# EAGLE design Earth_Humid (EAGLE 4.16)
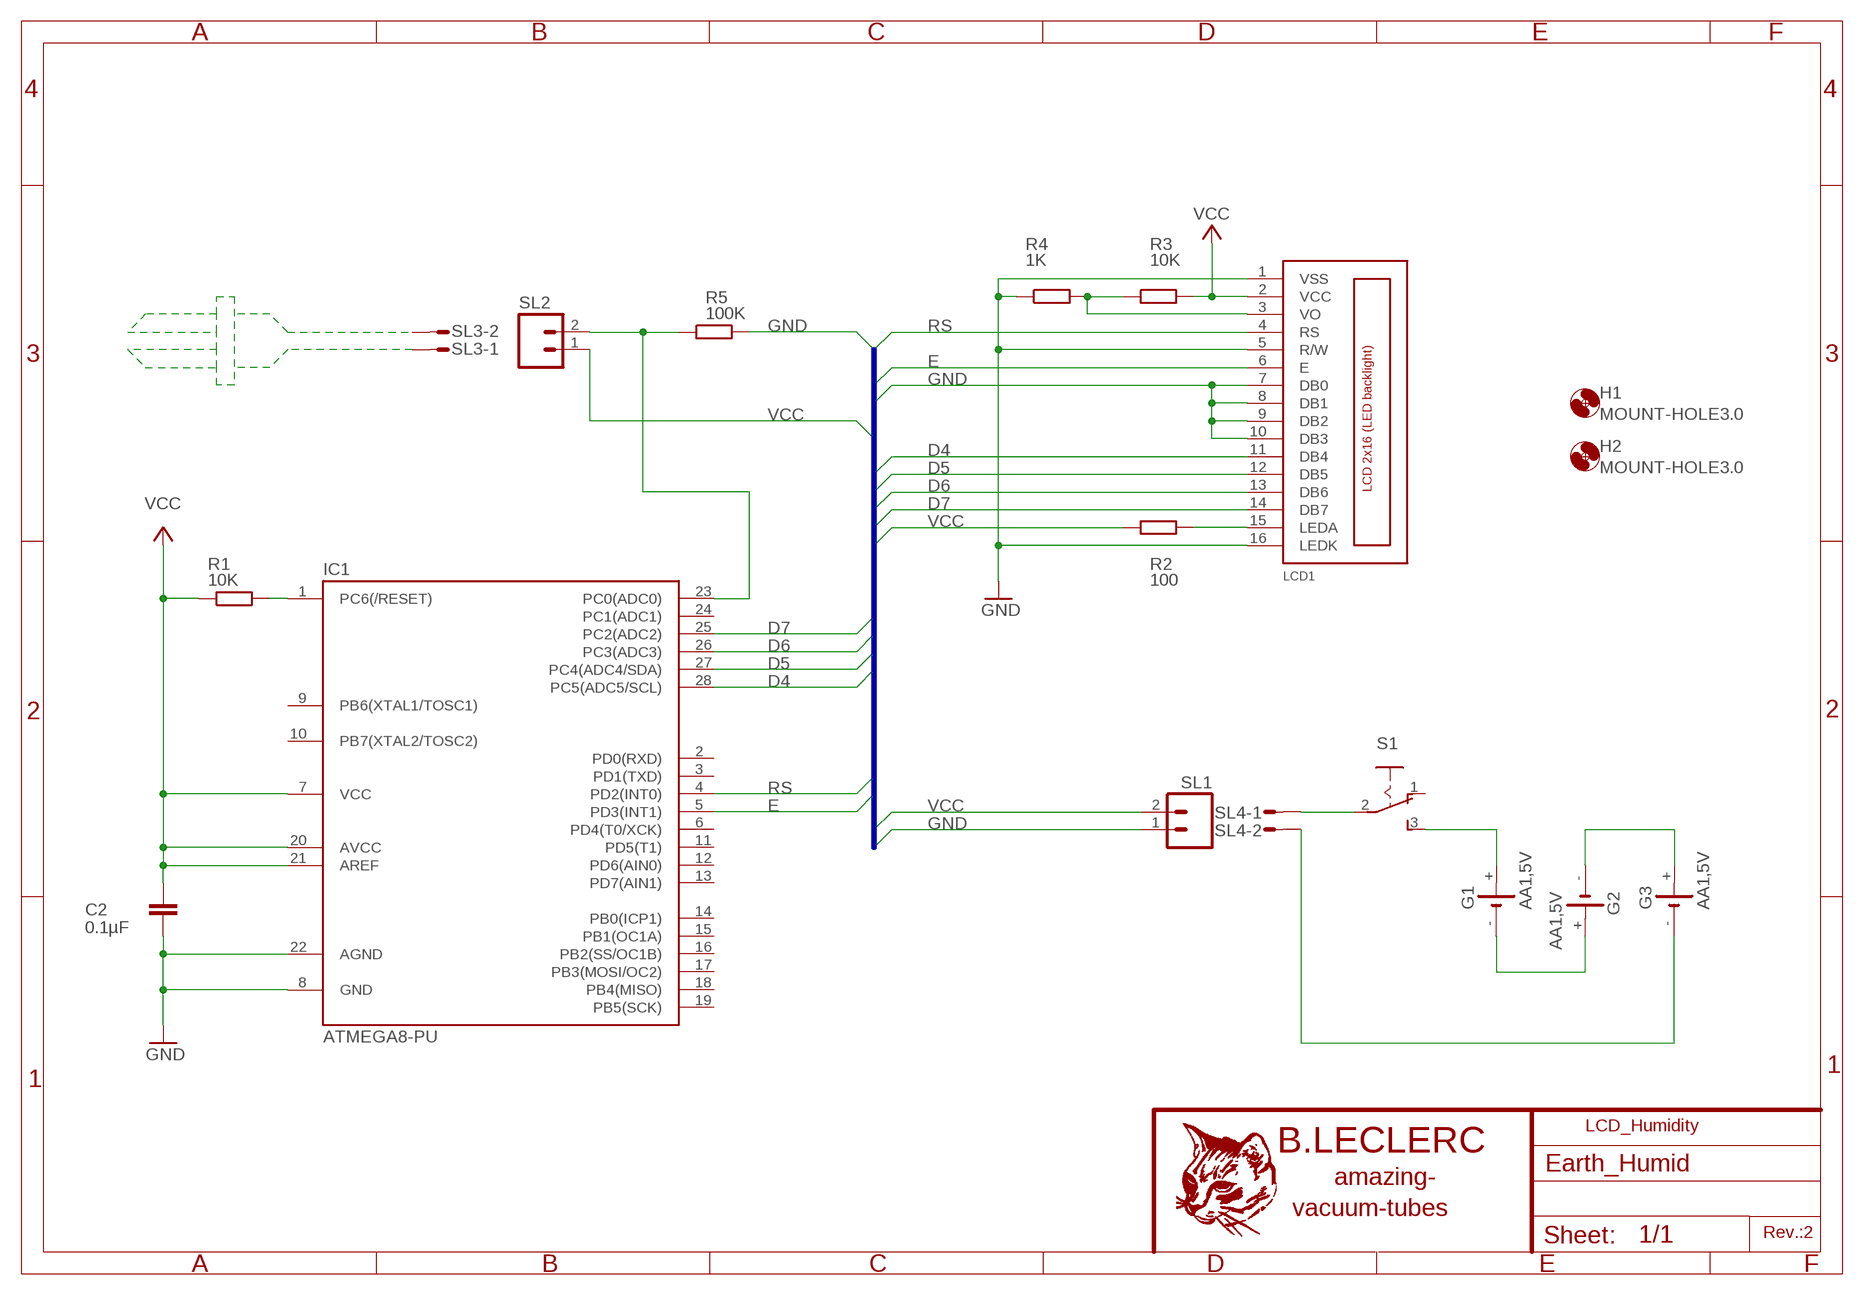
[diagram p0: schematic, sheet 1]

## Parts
C2  0.1µF  C-EU050-025X075  [C050-025X075]
G1  AA1,5V  SL-160AA/PR  [SL-160AA/PR]
G2  AA1,5V  SL-160AA/PR  [SL-160AA/PR]
G3  AA1,5V  SL-160AA/PR  [SL-160AA/PR]
H1  MOUNT-HOLE3.0  [3,0]
H2  MOUNT-HOLE3.0  [3,0]
IC1  ATMEGA8-PU  [DIL28-3]
LCD1  LCD_2X16_SIL  [HY-1602F]
R1  10K  R-EU_0207/10  [0207/10]
R2  100  R-EU_0207/10  [0207/10]
R3  10K  R-EU_0207/10  [0207/10]
R4  1K  R-EU_0207/10  [0207/10]
R5  100K  R-EU_0207/10  [0207/10]
S1  255SB  [255SB]
SL1  M02  [02P]
SL2  M02  [02P]
SL3  M02S  [02P]
SL4  M02S  [02P]

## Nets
D4: IC1.28(PC5(ADC5/SCL)) LCD1.11(DB4)
D5: IC1.27(PC4(ADC4/SDA)) LCD1.12(DB5)
D6: IC1.26(PC3(ADC3)) LCD1.13(DB6)
D7: IC1.25(PC2(ADC2)) LCD1.14(DB7)
E: IC1.5(PD3(INT1)) LCD1.6(E)
GND: C2.2 IC1.8(GND) IC1.22(AGND) LCD1.1(VSS) LCD1.5(R/W) LCD1.7(DB0) LCD1.8(DB1) LCD1.9(DB2) LCD1.10(DB3) LCD1.16(LEDK) R4.1 R5.2 SL1.1
N$1: S1.2(P) SL4.1
N$2: G1.+ S1.3(S)
N$3: IC1.1(PC6(/RESET)) R1.2
N$4: LCD1.3(VO) R3.1 R4.2
N$5: LCD1.15(LEDA) R2.2
N$6: IC1.23(PC0(ADC0)) R5.1 SL2.2
N$7: G1.- G2.+
N$8: G2.- G3.+
N$9: G3.- SL4.2
N$11: SL3.2
N$39: SL3.1
RS: IC1.4(PD2(INT0)) LCD1.4(RS)
VCC: C2.1 IC1.7(VCC) IC1.20(AVCC) IC1.21(AREF) LCD1.2(VCC) R1.1 R2.1 R3.2 SL1.2 SL2.1
Unconnected: IC1.2(PD0(RXD)) IC1.3(PD1(TXD)) IC1.6(PD4(T0/XCK)) IC1.9(PB6(XTAL1/TOSC1)) IC1.10(PB7(XTAL2/TOSC2)) IC1.11(PD5(T1)) IC1.12(PD6(AIN0)) IC1.13(PD7(AIN1)) IC1.14(PB0(ICP1)) IC1.15(PB1(OC1A)) IC1.16(PB2(SS/OC1B)) IC1.17(PB3(MOSI/OC2)) IC1.18(PB4(MISO)) IC1.19(PB5(SCK)) IC1.24(PC1(ADC1)) S1.1(O)

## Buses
B$1

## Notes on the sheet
- LCD_Humidity
- Rev.:2

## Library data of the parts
C2 = rcl:C-EU: CAPACITOR, European symbol
G1-G3 = battery:SL-160AA/PR: LI BATTERY Sonnenschein
H1 H2 = holes:MOUNT-HOLE: MOUNTING HOLE with drill center marker
IC1 = atmega8:ATMEGA8-PU
LCD1 = lcd_2x16_led_backlight:LCD_2X16_SIL
R1-R5 = rcl:R-EU_: RESISTOR, European symbol
S1 = switch:255SB: SLIDING SWITCH distributor Buerklin, 11G810
SL1 SL2 = con-NANARD:M02: AMP QUICK CONNECTOR
SL3 SL4 = con-NANARD:M02S: AMP QUICK CONNECTOR

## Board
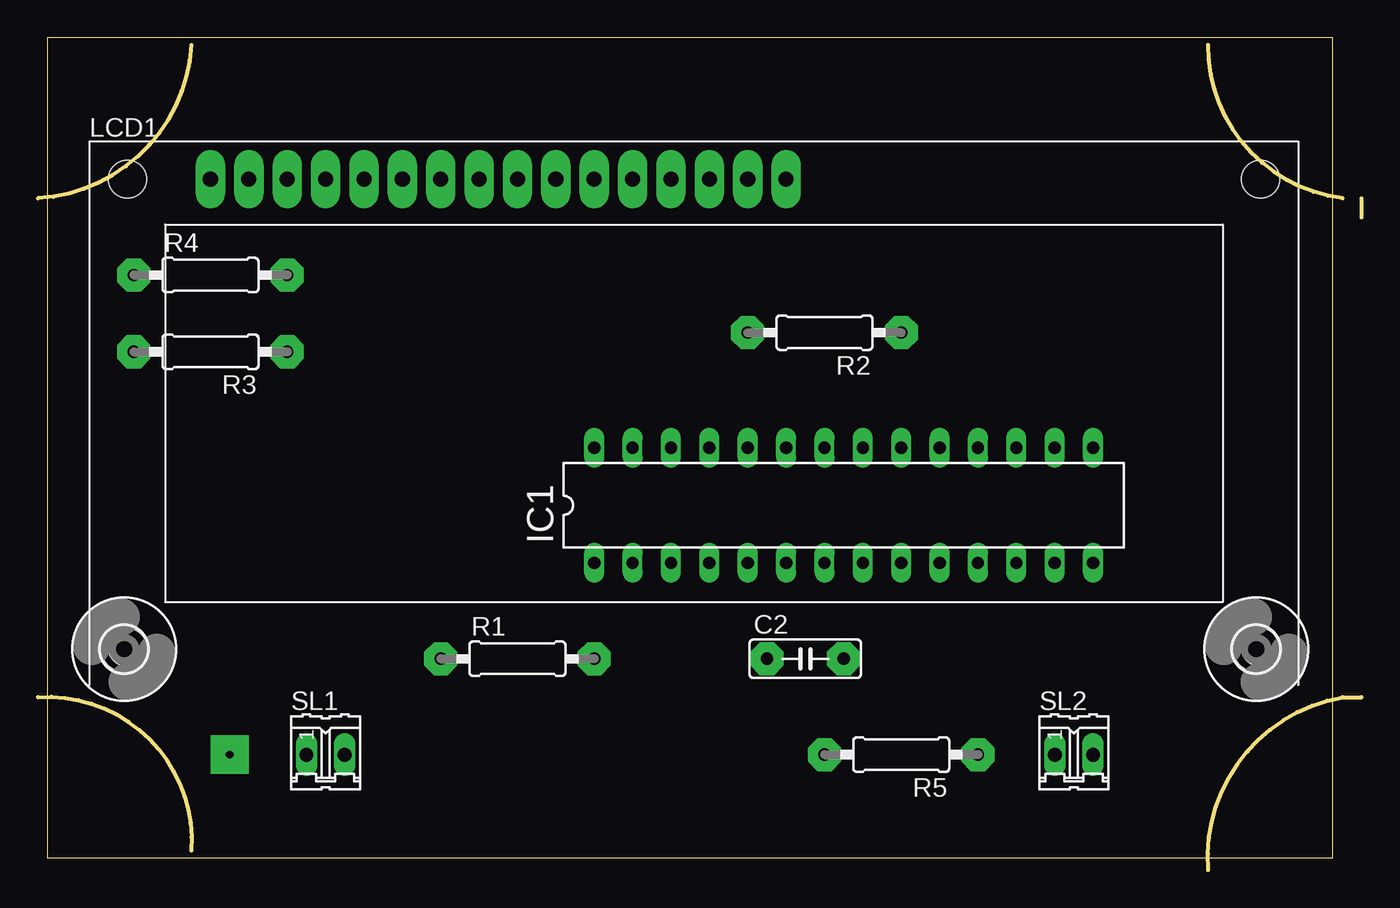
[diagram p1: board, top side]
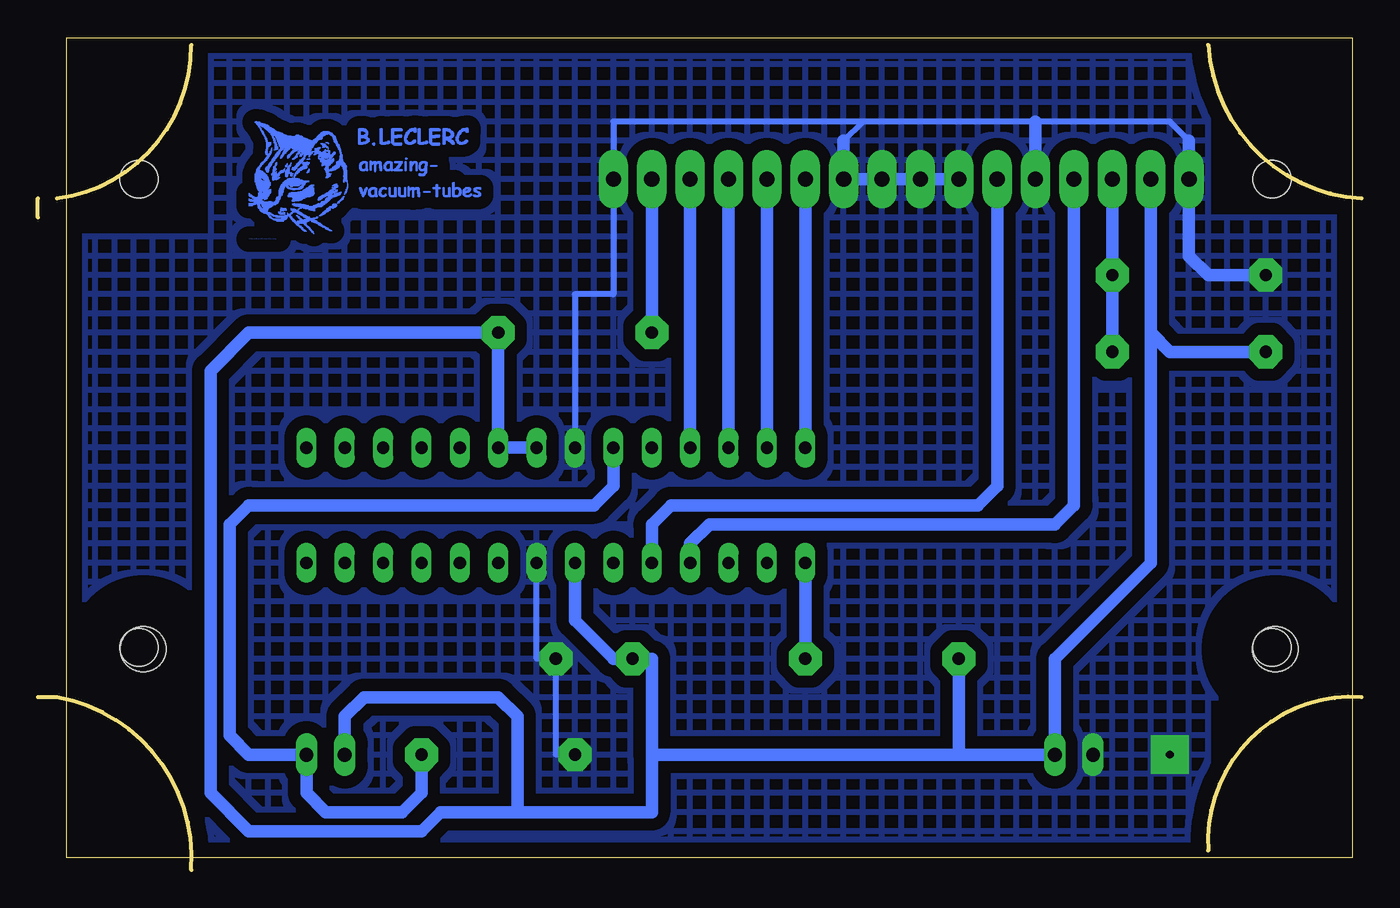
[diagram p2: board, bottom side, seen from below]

Size 87.63 x 55.08 mm. Coordinates in mm from the lower left corner, seen from the top.
Outline: 87.63,11.43 86.36,11.43 arc84 77.47,0
Outline: 87.63,43.18 87.63,44.45
Outline: 10.16,54.61 arc-83 0,44.45
Outline: 86.36,44.45 arc-83 77.47,54.61
Outline: 0,11.43 arc-98 10.16,1.27
Outline: 0.64,0.8 85.71,0.8 85.71,55.08 0.64,55.08 0.64,0.8
Copper layers (1*16): Top 0.035mm / dielectric 1.5mm / Bottom 0.035mm
Design rules "default": minimum track width 10mil, minimum drill 24mil, track to track 8mil, track to pad 8mil, pad to pad 8mil, via to via 8mil, smd to smd 8mil, copper to edge 40mil, drill to drill 8mil, minimum pad ring 10mil, minimum via ring 8mil, stop-mask expansion 4mil, vias tented up to drill 0mil, thermal gap 10mil

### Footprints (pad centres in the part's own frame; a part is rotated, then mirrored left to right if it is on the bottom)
C050-025X075 = drill 0.813 octagon: 1 -2.54,0; 2 2.54,0
SL-160AA/PR = drill 1.321 pad 3.15 octagon: + 25.273,0; - -25.4,0
3,0 = hole 3: 0,0
DIL28-3 = drill 0.813 long: 1 -16.51,-3.81; 2 -13.97,-3.81; 3 -11.43,-3.81; 4 -8.89,-3.81; 5 -6.35,-3.81; 6 -3.81,-3.81; 7 -1.27,-3.81; 8 1.27,-3.81; 9 3.81,-3.81; 10 6.35,-3.81; 11 8.89,-3.81; 12 11.43,-3.81; 13 13.97,-3.81; 14 16.51,-3.81; 15 16.51,3.81; 16 13.97,3.81; 17 11.43,3.81; 18 8.89,3.81; 19 6.35,3.81; 20 3.81,3.81; 21 1.27,3.81; 22 -1.27,3.81; 23 -3.81,3.81; 24 -6.35,3.81; 25 -8.89,3.81; 26 -11.43,3.81; 27 -13.97,3.81; 28 -16.51,3.81
HY-1602F = drill 1 pad 1.93 long: 1 2.54,0; 2 5.08,0; 3 7.62,0; 4 10.16,0; 5 12.7,0; 6 15.24,0; 7 17.78,0; 8 20.32,0; 9 22.86,0; 10 25.4,0; 11 27.94,0; 12 30.48,0; 13 33.02,0; 14 35.56,0; 15 38.1,0; 16 40.64,0 | hole 2.5: -2.96,0; 72.04,0; -2.96,-31; 72.04,-31
0207/10 = drill 0.813 octagon: 1 -5.08,0; 2 5.08,0
255SB = drill 1.118 long: 1 -3.81,0; 2 0,0; 3 3.81,0
02P = drill 0.914 long: 1 -1.27,0; 2 1.27,0

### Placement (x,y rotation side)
C2  50.8,13.97 0 top
G1  not placed on the board
G2  not placed on the board
G3  not placed on the board
H1  80.64,14.61 90 top
H2  5.71,14.61 90 top
IC1  53.34,24.13 0 top
LCD1  8.89,45.72 0 top
R1  31.75,13.97 0 top
R2  52.07,35.56 180 top
R3  11.43,34.29 180 top
R4  11.43,39.37 0 top
R5  57.15,7.62 180 top
S1  not placed on the board
SL1  19.05,7.62 0 top
SL2  68.58,7.62 0 top
SL3  not placed on the board
SL4  not placed on the board
U$2  [CHAT]  73.66,41.91 0 bottom

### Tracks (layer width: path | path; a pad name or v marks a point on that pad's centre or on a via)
D4
  Bottom 0.813: IC1.28 LCD1.11
D5
  Bottom 0.813: IC1.27 LCD1.12
D6
  Bottom 0.813: IC1.26 LCD1.13
D7
  Bottom 0.813: IC1.25 LCD1.14
E
  Bottom 0.813: LCD1.6 24.13,25.4 25.4,24.13 45.72,24.13 46.99,22.86 IC1.5
GND  (via drill 0.5 pad 1.27, 0.5 pad 1.93, 0.5 pad 2.18, 0.5 pad 2.54)
  Bottom 0.406: 33.02,49.53 21.59,49.53 12.7,49.53 11.43,48.26 | 33.02,49.53 34.29,48.26 | IC1.8 54.61,13.97 C2.2 53.34,7.62 R5.2 | IC1.22 52.07,38.1 49.53,38.1 LCD1.16 49.53,49.53 33.02,49.53
  Bottom 0.813: LCD1.7 LCD1.8 LCD1.9 LCD1.10 34.29,48.26 | 21.59,49.53 LCD1.5 | R4.1 10.16,39.37 11.43,40.64 LCD1.1 11.43,48.26
  other vias: 12.7,7.62 12.7,7.62 17.78,7.62 52.07,7.62 53.34,13.97 6.35,39.37 11.43,45.72 21.59,45.72 26.67,45.72 29.21,45.72 31.75,45.72 34.29,45.72 49.53,45.72 54.61,20.32 52.07,27.94
  pour Bottom (isolate 0.813, no thermals, hatched): 1.27,43.18 10.16,43.18 10.16,54.61 76.2,54.61 76.2,41.91 85.09,41.91 85.09,11.43 77.47,11.43 77.47,1.27 10.16,1.27 10.16,11.43 1.27,11.43
N$1  (1 unrouted)
N$2  (1 unrouted)
N$3
  Bottom 0.813: R1.2 IC1.1
N$4
  Bottom 0.813: LCD1.3 R4.2 R3.1
N$5
  Bottom 0.813: R2.2 LCD1.15
N$6  (via drill 0.6 pad 1.27)
  Bottom 0.813: R5.1 62.23,5.08 63.5,3.81 68.58,3.81 69.85,5.08 SL2.2 73.66,7.62 74.93,8.89 74.93,22.86 73.66,24.13 50.8,24.13 49.53,25.4 IC1.23
  other vias: 69.85,7.62 69.85,7.62
N$7  (1 unrouted)
N$8  (1 unrouted)
N$9  (1 unrouted)
N$10  (via drill 0.5 pad 1.27)
  other vias: 39.37,27.94
N$12  (via drill 0.5 pad 1.93)
  other vias: 13.97,45.72
N$13  (via drill 0.5 pad 1.93)
  other vias: 16.51,45.72
N$14  (via drill 0.5 pad 1.93)
  other vias: 19.05,45.72
N$16  (via drill 0.5 pad 1.93)
  other vias: 24.13,45.72
N$21  (via drill 0.5 pad 1.93)
  other vias: 36.83,45.72
N$22  (via drill 0.5 pad 1.93)
  other vias: 39.37,45.72
N$23  (via drill 0.5 pad 1.93)
  other vias: 41.91,45.72
N$24  (via drill 0.5 pad 1.93)
  other vias: 44.45,45.72
N$25  (via drill 0.5 pad 1.93)
  other vias: 46.99,45.72
N$27  (via drill 0.5 pad 1.27)
  other vias: 36.83,27.94
N$28  (via drill 0.5 pad 1.27)
  other vias: 41.91,27.94
N$29  (via drill 0.5 pad 1.27)
  other vias: 44.45,27.94
N$30  (via drill 0.5 pad 1.27)
  other vias: 46.99,27.94
N$31  (via drill 0.5 pad 1.27)
  other vias: 49.53,27.94
N$32  (via drill 0.5 pad 1.27)
  other vias: 49.53,27.94
N$34  (via drill 0.5 pad 1.27)
  other vias: 54.61,27.94
N$35  (via drill 0.5 pad 1.27)
  other vias: 57.15,27.94
N$36  (via drill 0.5 pad 1.27)
  other vias: 59.69,27.94
N$37  (via drill 0.5 pad 1.27)
  other vias: 62.23,27.94
N$38  (via drill 0.5 pad 1.27)
  other vias: 64.77,27.94
N$40  (via drill 0.5 pad 1.27)
  other vias: 67.31,27.94
N$41  (via drill 0.5 pad 1.27)
  other vias: 69.85,27.94
N$43  (via drill 0.5 pad 1.27)
  other vias: 36.83,20.32
N$44  (via drill 0.5 pad 1.27)
  other vias: 39.37,20.32
N$45  (via drill 0.5 pad 1.27)
  other vias: 41.91,20.32
N$46  (via drill 0.5 pad 1.27)
  other vias: 44.45,20.32
N$47  (via drill 0.5 pad 1.27)
  other vias: 46.99,20.32
N$48  (via drill 0.5 pad 1.27)
  other vias: 49.53,20.32
N$49  (via drill 0.5 pad 1.27)
  other vias: 52.07,20.32
N$51  (via drill 0.5 pad 1.27)
  other vias: 57.15,20.32
N$52  (via drill 0.5 pad 1.27)
  other vias: 59.69,20.32
N$53  (via drill 0.5 pad 1.27)
  other vias: 62.23,20.32
N$54  (via drill 0.5 pad 1.27)
  other vias: 64.77,20.32
N$55  (via drill 0.5 pad 1.27)
  other vias: 67.31,20.32
N$56  (via drill 0.5 pad 1.27)
  other vias: 69.85,20.32
N$57  (via drill 0.5 pad 2.18)
  other vias: 16.51,39.37
N$58  (via drill 0.5 pad 2.18)
  other vias: 6.35,34.29
N$60  (via drill 0.5 pad 2.18)
  other vias: 16.51,34.29
N$61  (via drill 0.5 pad 2.18)
  other vias: 46.99,35.56
N$62  (via drill 0.5 pad 2.18)
  other vias: 57.15,35.56
N$63  (via drill 0.5 pad 2.18)
  other vias: 36.83,13.97
N$64  (via drill 0.5 pad 2.18)
  other vias: 26.67,13.97
N$65  (via drill 0.5 pad 2.18)
  other vias: 48.26,13.97
N$68  (via drill 0.5 pad 2.18)
  other vias: 62.23,7.62
N$70  (via drill 0.5 pad 1.27)
  other vias: 20.32,7.62
N$71  (via drill 0.5 pad 1.27)
  other vias: 67.31,7.62
N$72  (via drill 0.5 pad 1.27)
  other vias: 69.85,7.62
RS
  Bottom 0.813: LCD1.4 19.05,24.13 20.32,22.86 43.18,22.86 44.45,21.59 IC1.4
VCC
  Bottom 0.813: IC1.21 IC1.20 R2.1 73.66,35.56 76.2,33.02 76.2,5.08 73.66,2.54 62.23,2.54 60.96,3.81 55.88,3.81 | 26.67,7.62 R1.1 | IC1.7 52.07,16.51 49.53,13.97 C2.1 46.99,13.97 46.99,7.62 | SL2.1 67.31,10.16 66.04,11.43 57.15,11.43 55.88,10.16 55.88,3.81 | 55.88,3.81 46.99,3.81 46.99,7.62 | 26.67,7.62 SL1.2 20.32,13.97 13.97,20.32 13.97,35.56 | 13.97,35.56 LCD1.2 | 13.97,35.56 12.7,34.29 R3.2 | 26.67,7.62 46.99,7.62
